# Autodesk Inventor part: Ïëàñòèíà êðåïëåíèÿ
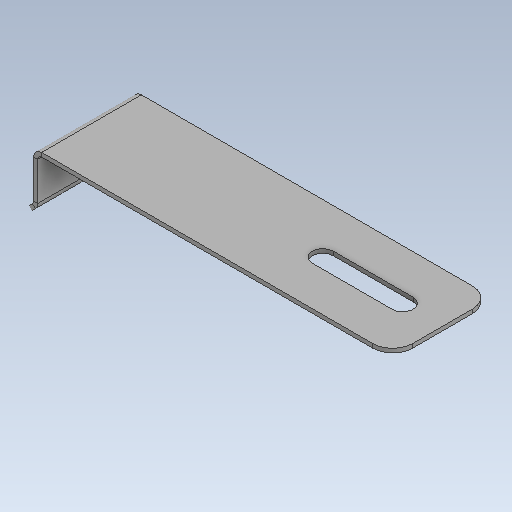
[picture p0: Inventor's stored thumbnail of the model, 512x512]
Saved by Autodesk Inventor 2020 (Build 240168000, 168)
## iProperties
Created: 1900-01
Part Number: Ïëàñòèíà êðåïëåíèÿ
Material: Générique
Document SubType Name: Modeling
Designer: bruno
Density: 1 g/cm^3
Appearance: Par défaut
Author: bruno
Revision Number: ANYUNSPECIFIED
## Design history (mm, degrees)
feature "Base1"
node "Solide1"
